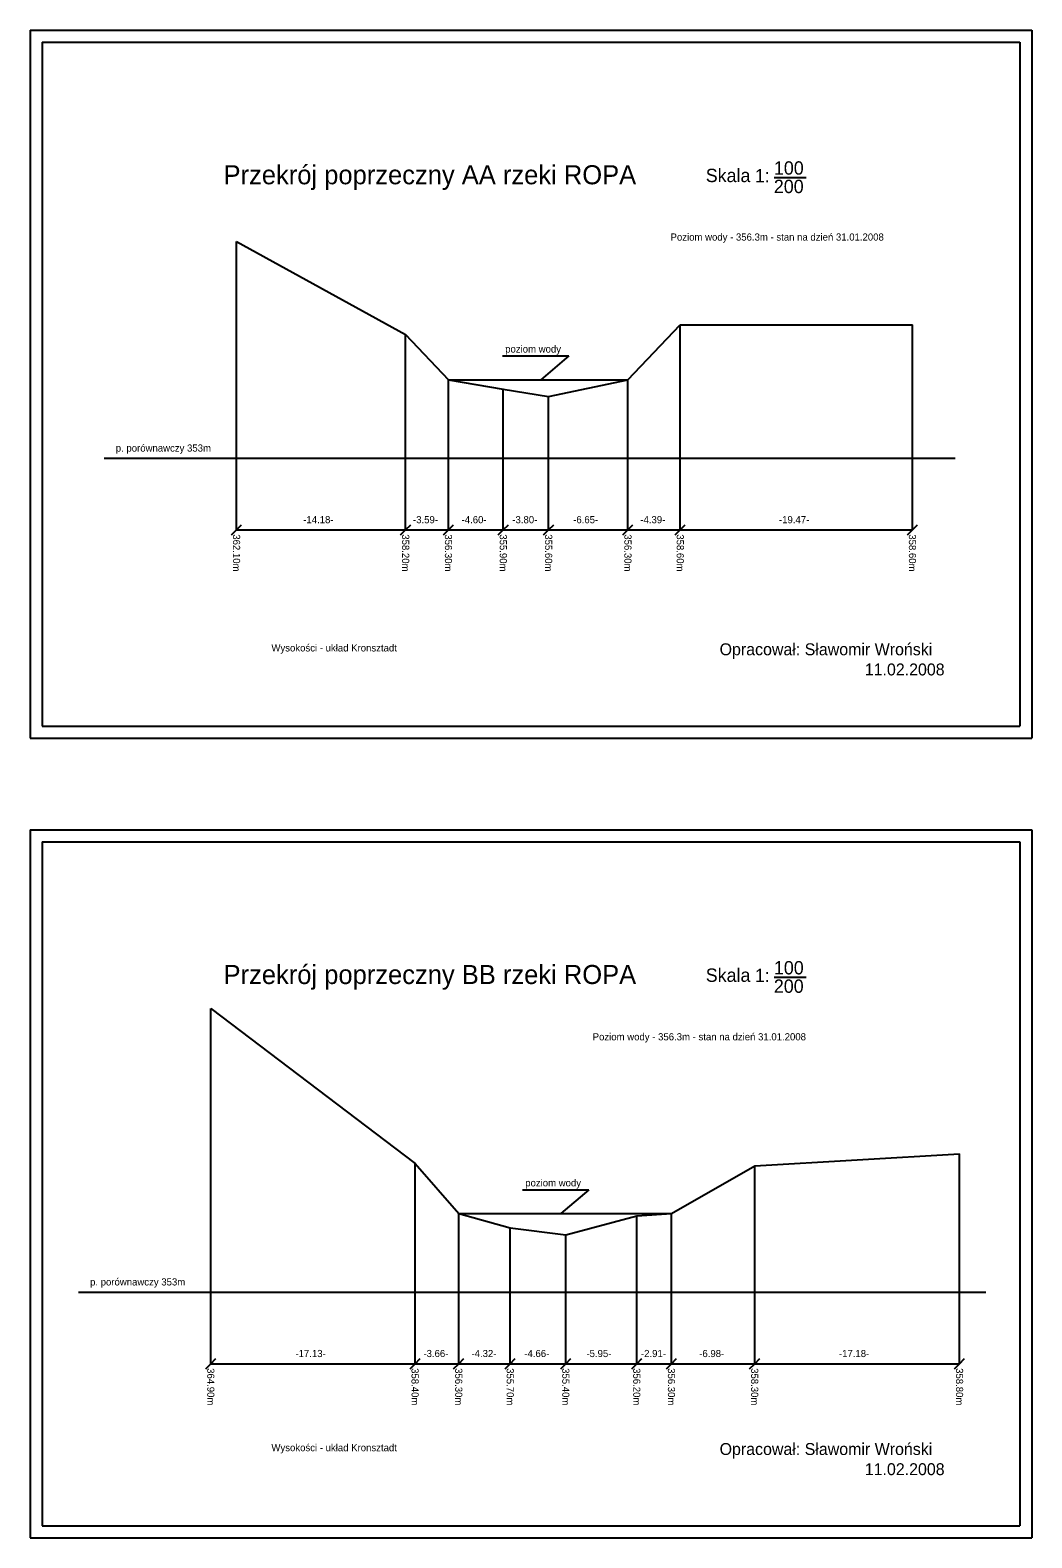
# Model space of a CAD drawing. Extents: x 746 to 788, y 74 to 202.
# Drawn here: x 745.5 to 787.5, y 138.5 to 201.8 of the extents above; entities that cross this region are included whole.
import ezdxf

# ---------------------------------------------------------------- set-up
doc = ezdxf.new("R2010")
doc.units = 0
doc.layers.add('Default', color=7, linetype='Continuous')
doc.layers.add('siatka', color=7, linetype='Continuous')

msp = doc.modelspace()

# ---------------------------------------------------------------- linework, layer by layer
at = {"layer": 'Default'}
for p, q in [((745.545, 201.785), (787.545, 201.785)), ((745.545, 201.785), (745.545, 172.085)), ((787.545, 201.785), (787.545, 172.085)), ((746.045, 201.285), (787.045, 201.285)), ((746.045, 201.285), (746.045, 172.585)), ((787.045, 201.285), (787.045, 172.585)), ((776.74, 195.606), (778.081, 195.606)), ((754.199, 180.822), (754.199, 192.922)), ((754.199, 192.922), (761.289, 189.022)), ((770.609, 187.122), (772.804, 189.422)), ((772.804, 180.822), (772.804, 189.422)), ((772.804, 189.422), (782.539, 189.422)), ((782.539, 180.822), (782.539, 189.422)), ((761.289, 180.822), (761.289, 189.022)), ((761.289, 189.022), (763.084, 187.122)), ((765.355, 188.117), (768.133, 188.117)), ((768.133, 188.117), (766.954, 187.122)), ((763.084, 180.822), (763.084, 187.122)), ((763.084, 187.122), (765.384, 186.722)), ((763.084, 187.122), (770.609, 187.122)), ((765.384, 180.822), (765.384, 186.722)), ((765.384, 186.722), (767.284, 186.422)), ((767.284, 186.422), (770.609, 187.122)), ((770.609, 180.822), (770.609, 187.122)), ((767.284, 180.822), (767.284, 186.422)), ((754.199, 180.822), (754.411, 181.034)), ((761.289, 180.822), (761.501, 181.034)), ((763.084, 180.822), (763.296, 181.034)), ((765.384, 180.822), (765.596, 181.034)), ((767.284, 180.822), (767.496, 181.034)), ((770.609, 180.822), (770.821, 181.034)), ((772.804, 180.822), (773.016, 181.034)), ((782.539, 180.822), (782.751, 181.034)), ((753.987, 180.61), (754.199, 180.822)), ((761.077, 180.61), (761.289, 180.822)), ((762.872, 180.61), (763.084, 180.822)), ((765.172, 180.61), (765.384, 180.822)), ((767.072, 180.61), (767.284, 180.822)), ((770.397, 180.61), (770.609, 180.822)), ((772.592, 180.61), (772.804, 180.822)), ((782.327, 180.61), (782.539, 180.822)), ((745.545, 172.085), (787.545, 172.085)), ((746.045, 172.585), (787.045, 172.585)), ((745.545, 168.235), (787.545, 168.235)), ((745.545, 168.235), (745.545, 138.535)), ((746.045, 167.735), (787.045, 167.735)), ((746.045, 167.735), (746.045, 139.035)), ((787.045, 167.735), (787.045, 139.035)), ((787.545, 168.235), (787.545, 138.535)), ((776.74, 162.056), (778.081, 162.056)), ((753.119, 145.841), (753.119, 160.741)), ((753.119, 160.741), (761.684, 154.241)), ((775.924, 154.141), (784.514, 154.641)), ((784.514, 145.841), (784.514, 154.641)), ((761.684, 145.841), (761.684, 154.241)), ((761.684, 154.241), (763.514, 152.141)), ((772.434, 152.141), (775.924, 154.141)), ((775.924, 145.841), (775.924, 154.141)), ((766.194, 153.136), (768.972, 153.136)), ((768.972, 153.136), (767.793, 152.141)), ((763.514, 152.141), (772.434, 152.141)), ((763.514, 145.841), (763.514, 152.141)), ((763.514, 152.141), (765.674, 151.541)), ((768.004, 151.241), (770.979, 152.041)), ((770.979, 152.041), (772.434, 152.141)), ((770.979, 145.841), (770.979, 152.041)), ((772.434, 145.841), (772.434, 152.141)), ((765.674, 145.841), (765.674, 151.541)), ((765.674, 151.541), (768.004, 151.241)), ((768.004, 145.841), (768.004, 151.241)), ((752.907, 145.629), (753.119, 145.841)), ((753.119, 145.841), (753.331, 146.053)), ((761.472, 145.629), (761.684, 145.841)), ((761.684, 145.841), (761.896, 146.053)), ((763.302, 145.629), (763.514, 145.841)), ((763.514, 145.841), (763.726, 146.053)), ((765.462, 145.629), (765.674, 145.841)), ((765.674, 145.841), (765.886, 146.053)), ((767.792, 145.629), (768.004, 145.841)), ((768.004, 145.841), (768.216, 146.053)), ((770.767, 145.629), (770.979, 145.841)), ((770.979, 145.841), (771.191, 146.053)), ((772.222, 145.629), (772.434, 145.841)), ((772.434, 145.841), (772.646, 146.053)), ((775.712, 145.629), (775.924, 145.841)), ((775.924, 145.841), (776.136, 146.053)), ((784.302, 145.629), (784.514, 145.841)), ((784.514, 145.841), (784.726, 146.053)), ((745.545, 138.535), (787.545, 138.535)), ((746.045, 139.035), (787.045, 139.035))]:
    msp.add_line(p, q, dxfattribs=at)
at = {"layer": 'siatka'}
for p, q in [((748.654, 183.822), (784.325, 183.822)), ((754.199, 180.822), (782.539, 180.822)), ((747.575, 148.841), (785.619, 148.841)), ((753.119, 145.841), (784.514, 145.841))]:
    msp.add_line(p, q, dxfattribs=at)

# ---------------------------------------------------------------- texts
at = {"layer": 'Default'}
for s, height, p in [('Przekrój poprzeczny AA rzeki ROPA', 0.8, (753.654, 195.319)), ('100', 0.56, (776.731, 195.723)), ('Skala', 0.56, (773.873, 195.41)), ('1:', 0.56, (775.933, 195.398)), ('200', 0.56, (776.728, 194.949)), ('Poziom wody - 356.3m - stan na dzień 31.01.2008', 0.3, (772.397, 192.956)), ('poziom wody', 0.3, (765.463, 188.259)), ('p. porównawczy 353m', 0.3, (749.135, 184.103)), ('-14.18-', 0.3, (756.995, 181.099)), ('-3.59-', 0.3, (761.598, 181.099)), ('-4.60-', 0.3, (763.635, 181.099)), ('-3.80-', 0.3, (765.762, 181.099)), ('-6.65-', 0.3, (768.314, 181.099)), ('-4.39-', 0.3, (771.13, 181.099)), ('-19.47-', 0.3, (776.943, 181.099)), ('Wysokości - układ Kronsztadt', 0.3, (755.661, 175.72)), ('Opracował: Sławomir Wroński', 0.5, (774.454, 175.561)), ('11.02.2008', 0.5, (780.541, 174.715)), ('Przekrój poprzeczny BB rzeki ROPA', 0.8, (753.654, 161.768)), ('100', 0.56, (776.731, 162.172)), ('Skala', 0.56, (773.873, 161.86)), ('1:', 0.56, (775.933, 161.848)), ('200', 0.56, (776.728, 161.399)), ('Poziom wody - 356.3m - stan na dzień 31.01.2008', 0.3, (769.132, 159.405)), ('poziom wody', 0.3, (766.303, 153.278)), ('p. porównawczy 353m', 0.3, (748.056, 149.122)), ('-17.13-', 0.3, (756.668, 146.118)), ('-3.66-', 0.3, (762.034, 146.118)), ('-4.32-', 0.3, (764.049, 146.118)), ('-4.66-', 0.3, (766.265, 146.118)), ('-5.95-', 0.3, (768.869, 146.118)), ('-2.91-', 0.3, (771.156, 146.118)), ('-6.98-', 0.3, (773.599, 146.118)), ('-17.18-', 0.3, (779.457, 146.118)), ('Wysokości - układ Kronsztadt', 0.3, (755.661, 142.169)), ('Opracował: Sławomir Wroński', 0.5, (774.454, 142.011)), ('11.02.2008', 0.5, (780.541, 141.165))]:
    msp.add_text(s, height=height, dxfattribs=at).set_placement(p)
for s, p in [('362.10m', (754.05, 180.634)), ('358.20m', (761.14, 180.634)), ('356.30m', (762.935, 180.634)), ('355.90m', (765.235, 180.634)), ('355.60m', (767.135, 180.634)), ('356.30m', (770.46, 180.634)), ('358.60m', (772.655, 180.634)), ('358.60m', (782.39, 180.634)), ('364.90m', (752.97, 145.653)), ('358.40m', (761.535, 145.653)), ('356.30m', (763.365, 145.653)), ('355.70m', (765.525, 145.653)), ('355.40m', (767.855, 145.653)), ('356.20m', (770.83, 145.653)), ('356.30m', (772.285, 145.653)), ('358.30m', (775.775, 145.653)), ('358.80m', (784.365, 145.653))]:
    msp.add_text(s, height=0.3, rotation=270, dxfattribs=at).set_placement(p)

doc.saveas('drawing.dxf')
